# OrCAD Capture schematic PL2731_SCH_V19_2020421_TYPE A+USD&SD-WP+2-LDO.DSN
size B; title: PL2731_SD & uSD Reader_USB3.0-A+2-LDO; rev: 1.9
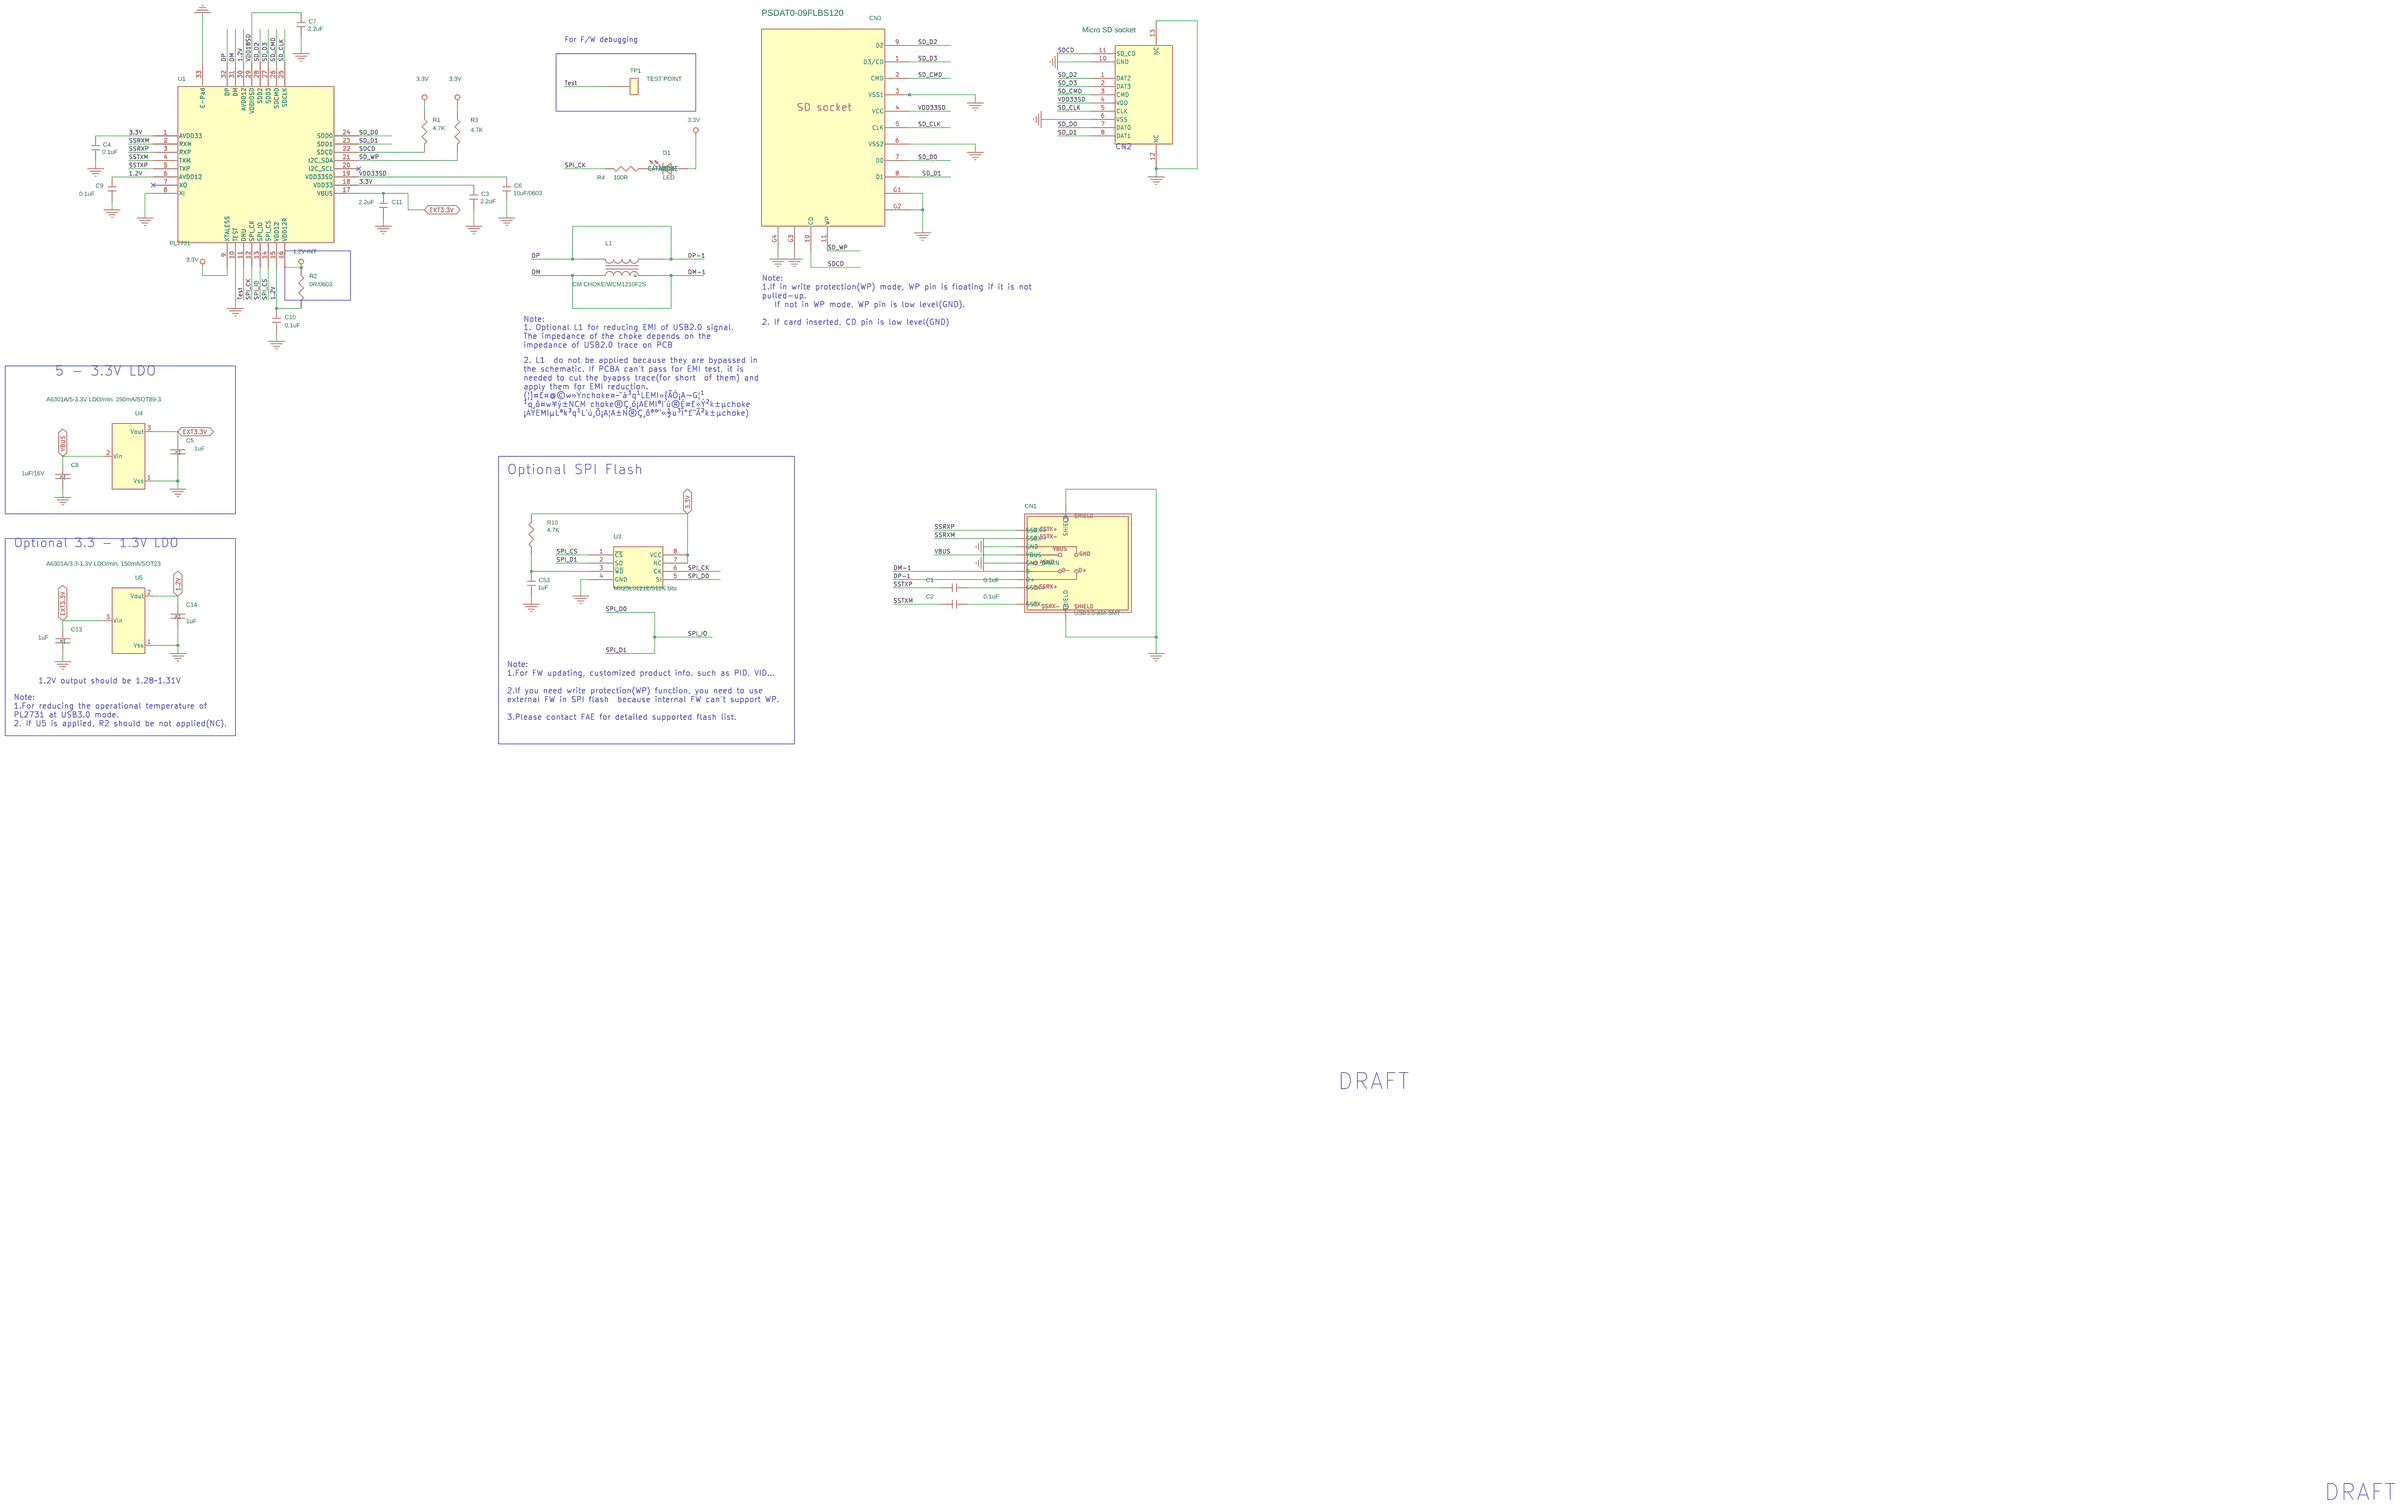
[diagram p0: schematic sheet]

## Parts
C1  0.1uF  [C0402]
C2  0.1uF  [C0402]
C3  2.2uF  [C0402]
C4  0.1uF  [C0402]
C5  1uF  [C0603]
C6  10uF/0603  [C0603]
C7  2.2uF  [C0402]
C8  1uF/16V  [C0603]
C9  0.1uF  [C0402]
C10  0.1uF  [C0402]
C11  2.2uF  [C0402]
C13  1uF  [C0603]
C14  1uF  [C0603]
C53  1uF  [C0603]
CN1  USB3.0-AM-SMT  [USB30_CON]
CN2  Micro SD socket  [T-FLASH_CON]
CN3  PSDAT0-09FLBS120  [s_sd-PSDAT0-09FLBS120]
D1  LED  [LED-0603]
L1  CM CHOKE/WCM1210F2S
R1  4.7K  [R0402]
R2  0R/0603  [R0603]
R3  4.7K  [R0402]
R4  100R  [R0402]
R10  4.7K  [R0402]
TP1  TEST POINT  [TP\SMD40]
U1  PL2731  [IC-QFN32-5X5-0.5]
U3  MX25L5121E/512K bits  [SOP8]
U4  A6301A/5-3.3V LDO/min. 250mA/SOT89-3  [A6115-B-SOT-223]
U5  A6301A/3.3-1.3V LDO/min. 150mA/SOT23  [A6115-B-SOT-223]

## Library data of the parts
C1-C4 C6 C7 C9-C11 C53 = CAP_1
C5 = CAP_NP_1
C8 = CAP_NP
C13 = CAP_NP_2
C14 = CAP_NP_3
CN1 = USB_3.0_B,Receptacle,90D,DIP_9P
CN2 = SDC013_2
CN3 = SD_MS_card_0
D1 = LED_1
L1 = CHOKE_CM_1
R1-R4 = R_0
R10 = R_4
TP1 = TEST_POINT
U1 = PL2731_QFN32_T5_1
U3 = 2402_4
U4 = CON6A_2
U5 = CON6A_3

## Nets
1.2V: C9.1 C10.1 C14.1 R2.2 U1.6(AVDD12) U1.15(VDD12) U1.30(AVDD12) U5.2(Vout)
1.2V-Int: R2.1 U1.16(VDD12R)
3.3V: C3.1 C4.1 D1.1(ANODE) R1.1 R3.1 R10.2 U1.1(AVDD33) U1.9(XTALESS) U1.18(VDD33) U3.7(NC) U3.8(VCC)
GND: C3.2 C4.2 C5.2 C6.2 C7.2 C8.2 C9.2 C10.2 C11.2 C13.2 C14.2 C53.2 CN1.4(GND) CN1.7(GND_DRAIN) CN1.10(SHIELD) CN1.11(SHIELD) CN2.6(VSS) CN2.10(GND) CN2.12(NC) CN2.13(NC) CN3.3(VSS1) CN3.6(VSS2) CN3.G1 CN3.G2 CN3.G3 CN3.G4 U1.8(XI) U1.10(TEST) U1.33(E-Pad) U3.4(GND) U4.1(Vss) U5.1(Vss)
VBUS: C8.1 CN1.1(VBUS) U4.2(Vin)
VDD18SD: C7.1 U1.29(VDDIOSD)
VDD33SD: C6.1 CN2.4(VDD) CN3.4(VCC) U1.19(VDD33SD)
DM: CN1.2(D-) L1.3(4) L1.4 U1.31(DM)
DP: CN1.3(D+) L1.1 L1.2 U1.32(DP)
EXT3.3V: C5.1 C11.1 C13.1 U1.17(VBUS) U4.3(Vout) U5.3(Vin)
SD_CLK: CN2.5(CLK) CN3.5(CLK) U1.25(SDCLK)
SD_CMD: CN2.3(CMD) CN3.2(CMD) U1.26(SDCMD)
SD_D0: CN2.7(DAT0) CN3.7(D0) U1.24(SDD0)
SD_D1: CN2.8(DAT1) CN3.8(D1) U1.23(SDD1)
SD_D2: CN2.1(DAT2) CN3.9(D2) U1.28(SDD2)
SD_D3: CN2.2(DAT3) CN3.1(D3/CD) U1.27(SDD3)
SD_WP: CN3.11(WP) R3.2 U1.21(I2C_SDA)
SDCD: CN2.11(SD_CD) CN3.10(CD) R1.2 U1.22(SDCD)
SPI_CK: R4.2 U1.12(SPI_CK) U3.6(CK)
SPI_CS: U1.14(SPI_CS) U3.1(~{CS})
SPI_D0: U1.13(SPI_IO) U3.2(SO) U3.5(SI)
SSRXM: CN1.8(SSRX-) U1.2(RXM)
SSRXP: CN1.9(SSRX+) U1.3(RXP)
SSTXM: C2.1 U1.4(TXM)
SSTXP: C1.1 U1.5(TXP)
Test: TP1.1 U1.11(DNU)
N16762084: C1.2 CN1.6(SSTX+)
N16762106: C2.2 CN1.5(SSTX-)
N16767995: C53.1 R10.1 U3.3(~{WD})
N16786708: D1.2(CATHODE) R4.1

Not connected (* = marked no-connect by the designer): U1 7(XO)* 20(I2C_SCL)*

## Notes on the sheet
- For F/W debugging
- CN2
- Note:
  1.If in write protection(WP) mode, WP pin is floating if it is not
  pulled-up.
     If not in WP mode, WP pin is low level(GND).
  2. If card inserted, CD pin is low level(GND)
- Note:
- 1. Optional L1 for reducing EMI of USB2.0 signal.
  The impedance of the choke depends on the
  impedance of USB2.0 trace on PCB
- 2. L1  do not be applied because they are bypassed in
  the schematic. If PCBA can't pass for EMI test, it is
  needed to cut the byapss trace(for short  of them) and
  apply them for EMI reduction.
  (¦]¤£¤@©w»Ý­nchoke¤~¯à³q¹LEMI»{ÃÒ¡A¬G¦¹
  ¹q¸ô¤w¥ý±NCM choke®Ç¸ô¡AEMIªì´ú®É¤£»Ý²k±µchoke
  ¡A­YEMIµLªk³q¹L´ú¸Õ¡A¦A±N®Ç¸ôªº¨«½u³Î°£¨Ã²k±µchoke)
- 5 - 3.3V LDO
- Optional SPI Flash
- Optional 3.3 - 1.3V LDO
- Note:
  1.For FW updating, customized product info. such as PID, VID...
  2.If you need write protection(WP) function, you need to use
  external FW in SPI flash  because internal FW can't support WP.
  3.Please contact FAE for detailed supported flash list.
- 1.2V output should be 1.28~1.31V
- Note:
  1.For reducing the operational temperature of
  PL2731 at USB3.0 mode.
  2. If U5 is applied, R2 should be not applied(NC).
- DRAFT
- DRAFT
